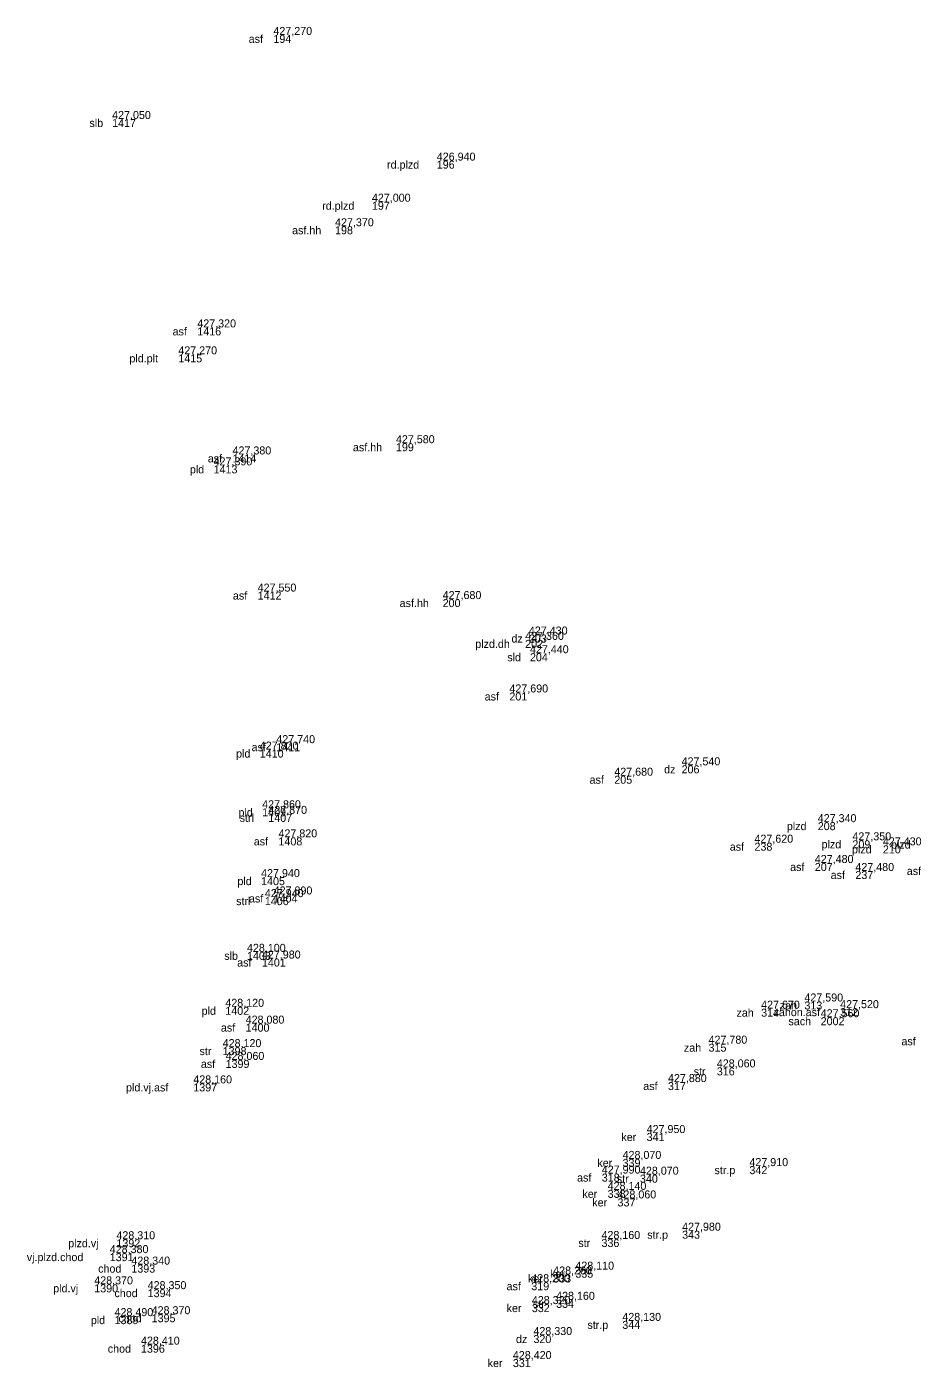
# Model space of a CAD drawing. Extents: x -747136 to -746138, y -1093274 to -1091717.
# Drawn here: x -746611.2 to -746577.7, y -1092934.5 to -1092884.2 of the extents above; entities that cross this region are included whole.
import ezdxf

# ---------------------------------------------------------------- set-up
doc = ezdxf.new("R2010")
doc.units = 0
for name, color, linetype in [('1029', 7, 'Continuous'), ('404', 7, 'Continuous'), ('424', 7, 'Continuous')]:
    doc.layers.add(name, color=color, linetype=linetype)

msp = doc.modelspace()

# ---------------------------------------------------------------- linework, layer by layer
at = {"layer": '404'}
for p, q in [((-746601.94, -1092884.53), (-746601.94, -1092884.53)), ((-746607.98, -1092887.68), (-746607.98, -1092887.68)), ((-746595.82, -1092889.24), (-746595.82, -1092889.24)), ((-746598.25, -1092890.78), (-746598.25, -1092890.78)), ((-746599.63, -1092891.7), (-746599.63, -1092891.7)), ((-746604.79, -1092895.49), (-746604.79, -1092895.49)), ((-746605.5, -1092896.5), (-746605.5, -1092896.5)), ((-746603.47, -1092900.25), (-746603.47, -1092900.25)), ((-746597.35, -1092899.83), (-746597.35, -1092899.83)), ((-746604.18, -1092900.66), (-746604.18, -1092900.66)), ((-746602.53, -1092905.39), (-746602.53, -1092905.39)), ((-746595.6, -1092905.67), (-746595.6, -1092905.67)), ((-746592.51, -1092907.2), (-746592.51, -1092907.2)), ((-746592.37, -1092907), (-746592.37, -1092907)), ((-746592.33, -1092907.7), (-746592.33, -1092907.7)), ((-746593.1, -1092909.17), (-746593.1, -1092909.17)), ((-746602.45, -1092911.31), (-746602.45, -1092911.31)), ((-746601.83, -1092911.07), (-746601.83, -1092911.07)), ((-746589.17, -1092912.29), (-746589.17, -1092912.29)), ((-746586.65, -1092911.9), (-746586.65, -1092911.9)), ((-746602.36, -1092913.51), (-746602.36, -1092913.51)), ((-746602.13, -1092913.72), (-746602.13, -1092913.72)), ((-746581.55, -1092914.03), (-746581.55, -1092914.03)), ((-746601.75, -1092914.6), (-746601.75, -1092914.6)), ((-746583.92, -1092914.8), (-746583.92, -1092914.8)), ((-746580.25, -1092914.71), (-746580.25, -1092914.71)), ((-746579.11, -1092914.9), (-746579.11, -1092914.9)), ((-746581.66, -1092915.56), (-746581.66, -1092915.56)), ((-746580.14, -1092915.86), (-746580.14, -1092915.86)), ((-746602.4, -1092916.09), (-746602.4, -1092916.09)), ((-746602.26, -1092916.84), (-746602.26, -1092916.84)), ((-746601.93, -1092916.74), (-746601.93, -1092916.74)), ((-746602.93, -1092918.89), (-746602.93, -1092918.89)), ((-746602.37, -1092919.14), (-746602.37, -1092919.14)), ((-746582.05, -1092920.75), (-746582.05, -1092920.75)), ((-746603.74, -1092920.95), (-746603.74, -1092920.95)), ((-746583.67, -1092921.02), (-746583.67, -1092921.02)), ((-746581.44, -1092921.34), (-746581.44, -1092921.34)), ((-746580.71, -1092921), (-746580.71, -1092921)), ((-746602.98, -1092921.58), (-746602.98, -1092921.58)), ((-746585.64, -1092922.33), (-746585.64, -1092922.33)), ((-746603.84, -1092922.46), (-746603.84, -1092922.46)), ((-746603.73, -1092922.94), (-746603.73, -1092922.94)), ((-746585.33, -1092923.22), (-746585.33, -1092923.22)), ((-746604.94, -1092923.82), (-746604.94, -1092923.82)), ((-746587.16, -1092923.77), (-746587.16, -1092923.77)), ((-746587.96, -1092925.68), (-746587.96, -1092925.68)), ((-746588.86, -1092926.65), (-746588.86, -1092926.65)), ((-746584.11, -1092926.92), (-746584.11, -1092926.92)), ((-746589.64, -1092927.2), (-746589.64, -1092927.2)), ((-746588.21, -1092927.24), (-746588.21, -1092927.24)), ((-746589.42, -1092927.81), (-746589.42, -1092927.81)), ((-746589.05, -1092928.13), (-746589.05, -1092928.13)), ((-746586.63, -1092929.34), (-746586.63, -1092929.34)), ((-746607.82, -1092929.66), (-746607.82, -1092929.66)), ((-746589.65, -1092929.65), (-746589.65, -1092929.65)), ((-746608.07, -1092930.18), (-746608.07, -1092930.18)), ((-746607.26, -1092930.61), (-746607.26, -1092930.61)), ((-746590.63, -1092930.8), (-746590.63, -1092930.8)), ((-746608.65, -1092931.35), (-746608.65, -1092931.35)), ((-746592.28, -1092931.27), (-746592.28, -1092931.27)), ((-746591.46, -1092930.98), (-746591.46, -1092930.98)), ((-746606.65, -1092931.53), (-746606.65, -1092931.53)), ((-746591.35, -1092931.93), (-746591.35, -1092931.93)), ((-746592.26, -1092932.09), (-746592.26, -1092932.09)), ((-746607.89, -1092932.54), (-746607.89, -1092932.54)), ((-746606.5, -1092932.47), (-746606.5, -1092932.47)), ((-746588.87, -1092932.72), (-746588.87, -1092932.72)), ((-746592.2, -1092933.25), (-746592.2, -1092933.25)), ((-746606.9, -1092933.61), (-746606.9, -1092933.61)), ((-746592.97, -1092934.15), (-746592.97, -1092934.15))]:
    msp.add_line(p, q, dxfattribs=at)

# ---------------------------------------------------------------- texts
at = {"layer": '1029'}
for s, p in [('427,270', (-746601.94, -1092884.53)), ('427,050', (-746607.98, -1092887.68)), ('426,940', (-746595.82, -1092889.24)), ('427,000', (-746598.25, -1092890.78)), ('427,370', (-746599.63, -1092891.7)), ('427,320', (-746604.79, -1092895.49)), ('427,270', (-746605.5, -1092896.5)), ('427,580', (-746597.35, -1092899.83)), ('427,380', (-746603.47, -1092900.25)), ('427,390', (-746604.18, -1092900.66)), ('427,550', (-746602.53, -1092905.39)), ('427,680', (-746595.6, -1092905.67)), ('427,430', (-746592.37, -1092907)), ('427,360', (-746592.51, -1092907.2)), ('427,440', (-746592.33, -1092907.7)), ('427,690', (-746593.1, -1092909.17)), ('427,740', (-746601.83, -1092911.07)), ('427,820', (-746602.45, -1092911.31)), ('427,540', (-746586.65, -1092911.9)), ('427,680', (-746589.17, -1092912.29)), ('427,860', (-746602.36, -1092913.51)), ('427,870', (-746602.13, -1092913.72)), ('427,340', (-746581.55, -1092914.03)), ('427,820', (-746601.75, -1092914.6)), ('427,620', (-746583.92, -1092914.8)), ('427,350', (-746580.25, -1092914.71)), ('427,430', (-746579.11, -1092914.9)), ('427,480', (-746581.66, -1092915.56)), ('427,940', (-746602.4, -1092916.09)), ('427,480', (-746580.14, -1092915.86)), ('427,940', (-746602.26, -1092916.84)), ('427,890', (-746601.93, -1092916.74)), ('428,100', (-746602.93, -1092918.89)), ('427,980', (-746602.37, -1092919.14)), ('428,120', (-746603.74, -1092920.95)), ('427,670', (-746583.67, -1092921.02)), ('427,590', (-746582.05, -1092920.75)), ('427,520', (-746580.71, -1092921)), ('428,080', (-746602.98, -1092921.58)), ('427,560', (-746581.44, -1092921.34)), ('428,120', (-746603.84, -1092922.46)), ('427,780', (-746585.64, -1092922.33)), ('428,060', (-746603.73, -1092922.94)), ('428,060', (-746585.33, -1092923.22)), ('428,160', (-746604.94, -1092923.82)), ('427,880', (-746587.16, -1092923.77)), ('427,950', (-746587.96, -1092925.68)), ('428,070', (-746588.86, -1092926.65)), ('427,990', (-746589.64, -1092927.2)), ('427,910', (-746584.11, -1092926.92)), ('428,070', (-746588.21, -1092927.24)), ('428,140', (-746589.42, -1092927.81)), ('428,060', (-746589.05, -1092928.13)), ('428,310', (-746607.82, -1092929.66)), ('428,160', (-746589.65, -1092929.65)), ('427,980', (-746586.63, -1092929.34)), ('428,380', (-746608.07, -1092930.18)), ('428,340', (-746607.26, -1092930.61)), ('428,260', (-746591.46, -1092930.98)), ('428,110', (-746590.63, -1092930.8)), ('428,370', (-746608.65, -1092931.35)), ('428,350', (-746606.65, -1092931.53)), ('428,200', (-746592.28, -1092931.27)), ('428,320', (-746592.26, -1092932.09)), ('428,160', (-746591.35, -1092931.93)), ('428,490', (-746607.89, -1092932.54)), ('428,370', (-746606.5, -1092932.47)), ('428,130', (-746588.87, -1092932.72)), ('428,330', (-746592.2, -1092933.25)), ('428,410', (-746606.9, -1092933.61)), ('428,420', (-746592.97, -1092934.15))]:
    msp.add_text(s, height=0.3, dxfattribs=at).set_placement(p)
at = {"layer": '424'}
for s, p in [(' asf', (-746602.977, -1092884.83)), ('194', (-746601.94, -1092884.83)), (' slb', (-746608.941, -1092887.98)), ('1417', (-746607.98, -1092887.98)), (' rd.plzd', (-746597.794, -1092889.54)), ('196', (-746595.82, -1092889.54)), (' rd.plzd', (-746600.224, -1092891.08)), ('197', (-746598.25, -1092891.08)), (' asf.hh', (-746601.352, -1092892)), ('198', (-746599.63, -1092892)), (' asf', (-746605.827, -1092895.79)), ('1416', (-746604.79, -1092895.79)), (' pld.plt', (-746607.444, -1092896.8)), ('1415', (-746605.5, -1092896.8)), (' asf', (-746604.507, -1092900.55)), ('1414', (-746603.47, -1092900.55)), (' asf.hh', (-746599.072, -1092900.13)), ('199', (-746597.35, -1092900.13)), (' pld', (-746605.179, -1092900.96)), ('1413', (-746604.18, -1092900.96)), (' asf', (-746603.567, -1092905.69)), ('1412', (-746602.53, -1092905.69)), (' asf.hh', (-746597.322, -1092905.97)), ('200', (-746595.6, -1092905.97)), (' plzd.dh', (-746594.489, -1092907.5)), (' dz', (-746593.135, -1092907.3)), ('202', (-746592.51, -1092907.5)), ('203', (-746592.37, -1092907.3)), (' sld', (-746593.291, -1092908)), ('204', (-746592.33, -1092908)), (' asf', (-746594.137, -1092909.47)), ('201', (-746593.1, -1092909.47)), (' pld', (-746603.449, -1092911.61)), (' asf', (-746602.867, -1092911.37)), ('1410', (-746602.45, -1092911.61)), ('1411', (-746601.83, -1092911.37)), (' asf', (-746590.207, -1092912.59)), ('205', (-746589.17, -1092912.59)), (' dz', (-746587.415, -1092912.2)), ('206', (-746586.65, -1092912.2)), (' pld', (-746603.359, -1092913.81)), (' strl', (-746603.316, -1092914.02)), ('1409', (-746602.36, -1092913.81)), ('1407', (-746602.13, -1092914.02)), (' plzd', (-746582.818, -1092914.33)), ('208', (-746581.55, -1092914.33)), (' asf', (-746602.787, -1092914.9)), ('1408', (-746601.75, -1092914.9)), (' asf', (-746584.957, -1092915.1)), ('238', (-746583.92, -1092915.1)), (' plzd', (-746581.518, -1092915.01)), ('209', (-746580.25, -1092915.01)), (' plzd', (-746578.918, -1092915.02)), (' plzd', (-746580.378, -1092915.2)), ('210', (-746579.11, -1092915.2)), (' asf', (-746582.697, -1092915.86)), ('207', (-746581.66, -1092915.86)), (' asf', (-746581.177, -1092916.16)), ('237', (-746580.14, -1092916.16)), (' asf', (-746578.327, -1092916.01)), (' pld', (-746603.399, -1092916.39)), ('1405', (-746602.4, -1092916.39)), (' strl', (-746603.446, -1092917.14)), (' asf', (-746602.967, -1092917.04)), ('1406', (-746602.26, -1092917.14)), ('1404', (-746601.93, -1092917.04)), (' slb', (-746603.891, -1092919.19)), ('1403', (-746602.93, -1092919.19)), (' asf', (-746603.407, -1092919.44)), ('1401', (-746602.37, -1092919.44)), (' zah', (-746583.085, -1092921.05)), ('313', (-746582.05, -1092921.05)), (' pld', (-746604.739, -1092921.25)), ('1402', (-746603.74, -1092921.25)), (' zah', (-746584.705, -1092921.32)), ('314', (-746583.67, -1092921.32)), (' zahon.asf', (-746583.317, -1092921.3)), (' sach', (-746582.758, -1092921.64)), ('2002', (-746581.44, -1092921.64)), ('312', (-746580.71, -1092921.3)), (' asf', (-746604.017, -1092921.88)), ('1400', (-746602.98, -1092921.88)), (' zah', (-746586.675, -1092922.63)), ('315', (-746585.64, -1092922.63)), (' asf', (-746578.527, -1092922.39)), (' str', (-746604.818, -1092922.76)), ('1398', (-746603.84, -1092922.76)), (' asf', (-746604.767, -1092923.24)), ('1399', (-746603.73, -1092923.24)), (' str', (-746586.308, -1092923.52)), ('316', (-746585.33, -1092923.52)), (' pld.vj.asf', (-746607.571, -1092924.12)), ('1397', (-746604.94, -1092924.12)), (' asf', (-746588.197, -1092924.07)), ('317', (-746587.16, -1092924.07)), (' ker', (-746589.016, -1092925.98)), ('341', (-746587.96, -1092925.98)), (' ker', (-746589.916, -1092926.95)), ('339', (-746588.86, -1092926.95)), ('342', (-746584.11, -1092927.22)), (' asf', (-746590.677, -1092927.5)), ('318', (-746589.64, -1092927.5)), (' str', (-746589.188, -1092927.54)), ('340', (-746588.21, -1092927.54)), (' str.p', (-746585.529, -1092927.22)), (' ker', (-746590.476, -1092928.11)), ('338', (-746589.42, -1092928.11)), (' ker', (-746590.106, -1092928.43)), ('337', (-746589.05, -1092928.43)), (' str.p', (-746588.049, -1092929.64)), ('343', (-746586.63, -1092929.64)), (' plzd.vj', (-746609.738, -1092929.96)), ('1392', (-746607.82, -1092929.96)), (' str', (-746590.628, -1092929.95)), ('336', (-746589.65, -1092929.95)), (' vj.plzd.chod', (-746611.289, -1092930.48)), ('1391', (-746608.07, -1092930.48)), (' chod', (-746608.616, -1092930.91)), ('1393', (-746607.26, -1092930.91)), (' ker', (-746591.686, -1092931.1)), ('335', (-746590.63, -1092931.1)), (' pld.vj', (-746610.299, -1092931.65)), ('1390', (-746608.65, -1092931.65)), (' asf', (-746593.317, -1092931.57)), (' ker', (-746592.516, -1092931.28)), ('319', (-746592.28, -1092931.57)), ('333', (-746591.46, -1092931.28)), (' chod', (-746608.006, -1092931.83)), ('1394', (-746606.65, -1092931.83)), (' str', (-746592.328, -1092932.23)), ('334', (-746591.35, -1092932.23)), (' ker', (-746593.316, -1092932.39)), ('332', (-746592.26, -1092932.39)), (' pld', (-746608.889, -1092932.84)), ('1389', (-746607.89, -1092932.84)), (' chod', (-746607.856, -1092932.77)), ('1395', (-746606.5, -1092932.77)), (' str.p', (-746590.289, -1092933.02)), ('344', (-746588.87, -1092933.02)), (' dz', (-746592.965, -1092933.55)), ('320', (-746592.2, -1092933.55)), (' chod', (-746608.256, -1092933.91)), ('1396', (-746606.9, -1092933.91)), (' ker', (-746594.026, -1092934.45)), ('331', (-746592.97, -1092934.45))]:
    msp.add_text(s, height=0.3, dxfattribs=at).set_placement(p)

doc.saveas('drawing.dxf')
